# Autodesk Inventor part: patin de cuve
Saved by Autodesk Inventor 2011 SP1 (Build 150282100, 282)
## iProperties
Created: 2010-12
Part Number: patin de cuve
Document SubType Name: Modeling
Designer: eric
Density: 1 g/cm^3
Author: eric
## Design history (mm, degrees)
feature "Base1"
node "Solide1"
node "Corps solides"
node "Corps surfaciques"
